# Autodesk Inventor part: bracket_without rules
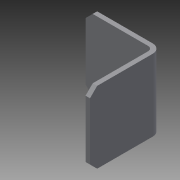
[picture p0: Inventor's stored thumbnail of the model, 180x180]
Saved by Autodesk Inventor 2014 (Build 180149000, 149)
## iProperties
Created: 2007-08
Part Number: bracket_without rules
Document SubType Name: Modeling
Designer: DaveR
Density: 1 g/cm^3
Mass: 7.59456 g
Surface Area: 56.7093 cm^2
Volume: 7.59456 cm^3
Material: Generic
Appearance: Default
RuleStatus: InUse
Author: DaveR
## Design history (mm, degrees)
sketch "Sketch1"
  geometry: L1 (-3.311, 44.86)-(-3.311, -5.94); L2 (-3.311, -5.94)-(47.489, -5.94); L3 (47.489, -5.94)-(47.489, -2.765); L4 (47.489, -2.765)-(-0.136, -2.765); L5 (-0.136, -2.765)-(-0.136, 44.86); L6 (-0.136, 44.86)-(-3.311, 44.86)
  constraints: 12 end point, 2 parallel, 2 perpendicular, 1 vertical
  dimensions: "base_thickness" = 3.175 distance of L2.end L3.end; "flange_thickness" = 3.175 distance of L5.end L1.start; "base_length" = 50.8 distance of L1.end L2.end; "flange_height" = 50.8 distance of L1.start L1.end
extrude "main_body" new body sketch "Sketch1" taper "draft_dont_use" = 0 deg; stored distance "bracket_width" = 50.8
chamfer "Chamfers" distance "chamfer" = 5.08; stored, may be unused: second distance "d25" = 3.175, angle "d26" = 45 deg
hole "base_hole" diameter "base_hole_dia" = 6.35; stored, may be unused: countersink angle "d12" = 82 deg, drill point angle "d14" = 118 deg; dims "d9" = 12.7, "d10" = 9.525, "d11" = 6.35, "d13" = 19.05, "base_hole_width_loc" = 25.4 (= 0.5 x bracket_width), "base_hole_length_loc" = 15.875 (computed from base_length)
pattern_linear "base_hole_pattern" dims "spacing_between_base_holes" = 19.05 (= 0.5 x bracket_width - base_hole_dia)
hole "flange_hole" diameter "flange_hole_dia" = 6.35 (= base_hole_dia); stored, may be unused: countersink angle "d21" = 82 deg, drill point angle "d23" = 118 deg; dims "d18" = 12.7, "d19" = 9.525, "d20" = 6.35, "d22" = 19.05, "flange_hole_width_loc" = 25.4 (= 0.5 x bracket_width), "flange_hole_length_loc" = 15.875 (computed from flange_height)
pattern_linear "flange_hole_pattern" dims "spacing_between_flange_holes" = 19.05 (= 0.5 x bracket_width - flange_hole_dia)
fillet "Inside_fillet" dims "inside_rad" = 3.175
fillet "Outside_fillet" dims "outside_rad" = 6.35 (= inside_rad + flange_thickness)
sketch "Sketch2"
  geometry: L1 (-0.136, 9.935)-(12.564, -2.765); L2 (-0.136, 39.78)-(-0.136, 0.41) reference; L3 (3.039, -2.765)-(42.409, -2.765) reference; 2 further points
  constraints: 2 end point, 2 point on line
  dimensions: "rib_angle" = 45 deg angle of L3 L1; "rib_height" = 12.7 distance from line of L3 L1.start
feature "center_rib" sketch "Sketch2" dims "d31" = 2.54, "rib_thickness" = 2.38125 (= 0.75 x flange_thickness), "rib_draft_dont_use" = 0
pattern_linear "rib_pattern" dims "spacing_between_ribs" = 10.31875
body "Solid1"
